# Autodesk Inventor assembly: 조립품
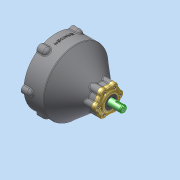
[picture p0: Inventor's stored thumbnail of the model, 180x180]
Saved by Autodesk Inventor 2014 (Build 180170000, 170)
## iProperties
Created: 2026-05
Part Number: 조립품
Document SubType Name: Assembly
Designer: dg
Author: dg
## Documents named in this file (19)
- C:\Users\dg\Desktop\760503v1007\조립품.iam
- C:\Users\dg\Desktop\760503v1007\본체.ipt
- C:\Users\dg\Desktop\760503v1007\가져온 구성요소\6각 구멍붙이 볼트 M4x10\6각 구멍붙이 볼트 M4x10.ipt
- C:\Users\dg\Desktop\760503v1007\가져온 구성요소\6각 구멍붙이 볼트 M4x20\6각 구멍붙이 볼트 M4x20.ipt
- C:\Users\dg\Desktop\760503v1007\가져온 구성요소\6각 구멍붙이 볼트 M6x10\6각 구멍붙이 볼트 M6x10.ipt
- C:\Users\dg\Desktop\760503v1007\가져온 구성요소\깊은 홈 볼 베어링 6010\깊은 홈 볼 베어링 6010.ipt
- C:\Users\dg\Desktop\760503v1007\가져온 구성요소\깊은 홈 볼 베어링 6203\깊은 홈 볼 베어링 6203.ipt
- C:\Users\dg\Desktop\760503v1007\가져온 구성요소\깊은 홈 볼 베어링 6900\깊은 홈 볼 베어링 6900.ipt
- C:\Users\dg\Desktop\760503v1007\가져온 구성요소\링 기어\링 기어.ipt
- C:\Users\dg\Desktop\760503v1007\가져온 구성요소\선 기어 축\선 기어 축.ipt
- C:\Users\dg\Desktop\760503v1007\가져온 구성요소\엔드 캡\엔드 캡.ipt
- C:\Users\dg\Desktop\760503v1007\가져온 구성요소\오일 실 17 32 8\오일 실 17 32 8.ipt
- C:\Users\dg\Desktop\760503v1007\가져온 구성요소\유성 기어\유성 기어.ipt
- C:\Users\dg\Desktop\760503v1007\가져온 구성요소\유성 축\유성 축.ipt
- C:\Users\dg\Desktop\760503v1007\가져온 구성요소\유성 캐리어 커버\유성 캐리어 커버.ipt
- C:\Users\dg\Desktop\760503v1007\가져온 구성요소\유성 캐리어\유성 캐리어.ipt
- C:\Users\dg\Desktop\760503v1007\가져온 구성요소\축용 C형 멈춤링 17\축용 C형 멈춤링 17.ipt
- C:\Users\dg\Desktop\760503v1007\가져온 구성요소\칼라\칼라.ipt
- C:\Users\dg\Desktop\760503v1007\가져온 구성요소\커버\커버.ipt
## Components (18 placed, 3 different names)
1. 6각 구멍붙이 볼트 M4x10:1
2. 6각 구멍붙이 볼트 M4x10:3
3. 6각 구멍붙이 볼트 M4x10:4
4. 6각 구멍붙이 볼트 M6x10:2
5. 6각 구멍붙이 볼트 M6x10:3
6. 6각 구멍붙이 볼트 M6x10:4
7. 6각 구멍붙이 볼트 M4x20:1
8. 6각 구멍붙이 볼트 M4x20:2
9. 6각 구멍붙이 볼트 M4x20:3
10. 6각 구멍붙이 볼트 M4x20:4
11. 6각 구멍붙이 볼트 M4x20:5
12. 6각 구멍붙이 볼트 M4x20:6
13. 6각 구멍붙이 볼트 M4x10:2
14. 6각 구멍붙이 볼트 M4x10:5
15. 6각 구멍붙이 볼트 M4x10:6
16. 6각 구멍붙이 볼트 M4x10:7
17. 6각 구멍붙이 볼트 M4x10:8
18. 6각 구멍붙이 볼트 M4x10:9
